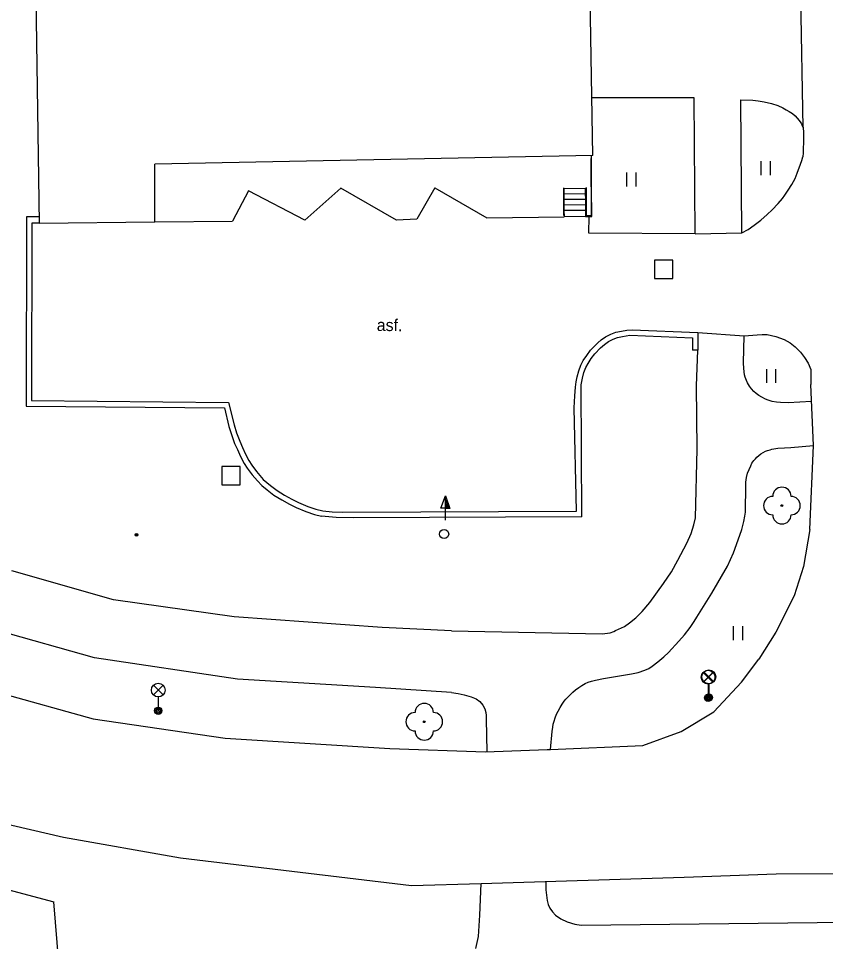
# Model space of a CAD drawing. Extents: x -641829 to -641525, y -1114855 to -1114359.
# Drawn here: x -641625.7 to -641581.7, y -1114535.8 to -1114485.6 of the extents above; entities that cross this region are included whole.
import ezdxf

# ---------------------------------------------------------------- set-up
doc = ezdxf.new("R2010")
doc.units = 0
for name, color, linetype in [('Vrstva 10', 7, 'Continuous'), ('Vrstva 11', 7, 'Continuous'), ('Vrstva 20', 7, 'Continuous'), ('Vrstva 22', 7, 'Continuous'), ('Vrstva 25', 7, 'Continuous'), ('Vrstva 26', 7, 'Continuous'), ('Vrstva 28', 7, 'Continuous'), ('Vrstva 33', 7, 'Continuous'), ('Vrstva 36', 7, 'Continuous'), ('Vrstva 40', 7, 'Continuous'), ('Vrstva 5', 7, 'Continuous'), ('Vrstva 9', 7, 'Continuous')]:
    doc.layers.add(name, color=color, linetype=linetype)

msp = doc.modelspace()

# ---------------------------------------------------------------- linework, layer by layer
at = {"layer": 'Vrstva 10'}
for p, q in [((-641582.96, -1114491.51), (-641583.23, -1114475.12)), ((-641582.96, -1114491.51), (-641582.94, -1114491.78)), ((-641582.94, -1114491.78), (-641582.93, -1114492.28)), ((-641582.93, -1114492.28), (-641582.95, -1114492.71)), ((-641582.95, -1114492.71), (-641582.95, -1114492.89)), ((-641583.09, -1114493.51), (-641583.02, -1114493.3)), ((-641583.02, -1114493.3), (-641582.97, -1114493.1)), ((-641582.95, -1114492.89), (-641582.97, -1114493.1)), ((-641583.27, -1114493.99), (-641583.09, -1114493.51)), ((-641583.57, -1114494.61), (-641583.39, -1114494.29)), ((-641583.39, -1114494.29), (-641583.27, -1114493.99)), ((-641583.76, -1114494.92), (-641583.57, -1114494.61)), ((-641584.08, -1114495.37), (-641583.95, -1114495.19)), ((-641583.95, -1114495.19), (-641583.76, -1114494.92)), ((-641584.64, -1114496), (-641584.31, -1114495.64)), ((-641584.31, -1114495.64), (-641584.08, -1114495.37)), ((-641585.25, -1114496.56), (-641584.91, -1114496.25)), ((-641584.91, -1114496.25), (-641584.64, -1114496)), ((-641594.62, -1114497.26), (-641594.61, -1114496.36)), ((-641585.62, -1114496.83), (-641585.25, -1114496.56)), ((-641588.83, -1114497.3), (-641594.62, -1114497.26)), ((-641588.83, -1114497.3), (-641586.3, -1114497.24)), ((-641586.3, -1114497.24), (-641585.95, -1114497.06)), ((-641585.95, -1114497.06), (-641585.62, -1114496.83)), ((-641588.68, -1114502.68), (-641586.16, -1114502.85)), ((-641586.16, -1114502.85), (-641585.46, -1114502.8)), ((-641585.46, -1114502.8), (-641585.19, -1114502.78)), ((-641585.19, -1114502.78), (-641584.92, -1114502.79)), ((-641582.39, -1114508.83), (-641582.54, -1114505.5)), ((-641582.58, -1114513.41), (-641582.39, -1114508.83)), ((-641582.58, -1114513.41), (-641582.94, -1114515.41)), ((-641582.94, -1114515.41), (-641583.45, -1114517.02)), ((-641583.45, -1114517.02), (-641584.44, -1114519)), ((-641584.44, -1114519), (-641585.36, -1114520.47)), ((-641586.31, -1114521.71), (-641585.36, -1114520.47)), ((-641627.95, -1114521.94), (-641621.63, -1114523.72)), ((-641587.81, -1114523.33), (-641586.31, -1114521.71)), ((-641589.6, -1114524.4), (-641587.81, -1114523.33)), ((-641621.63, -1114523.72), (-641614.43, -1114524.77)), ((-641591.69, -1114525.17), (-641589.6, -1114524.4)), ((-641614.43, -1114524.77), (-641605.47, -1114525.32)), ((-641605.47, -1114525.32), (-641600.26, -1114525.51)), ((-641600.26, -1114525.51), (-641596.9, -1114525.39)), ((-641633.98, -1114527.66), (-641623.24, -1114530.15)), ((-641623.24, -1114530.15), (-641616.87, -1114531.28)), ((-641616.87, -1114531.28), (-641604.29, -1114532.79)), ((-641628.25, -1114532.49), (-641623.76, -1114533.67)), ((-641589.44, -1114532.34), (-641584.42, -1114532.15)), ((-641584.42, -1114532.15), (-641572.24, -1114532.1)), ((-641622.14, -1114553.93), (-641623.76, -1114533.67))]:
    msp.add_line(p, q, dxfattribs=at)
for points in [[(-641596.9, -1114525.39), (-641596.71, -1114525.38), (-641591.69, -1114525.17)], [(-641604.29, -1114532.79), (-641600.49, -1114532.67), (-641589.44, -1114532.34)]]:
    msp.add_lwpolyline(points, dxfattribs=at)
at = {"layer": 'Vrstva 11'}
for p, q in [((-641588.88, -1114489.9), (-641594.45, -1114489.9)), ((-641588.83, -1114497.3), (-641588.88, -1114489.9)), ((-641586.3, -1114497.24), (-641586.35, -1114490)), ((-641586.35, -1114490), (-641585.7, -1114490.02)), ((-641585.7, -1114490.02), (-641585.4, -1114490.05)), ((-641585.4, -1114490.05), (-641585.08, -1114490.11)), ((-641585.08, -1114490.11), (-641584.67, -1114490.21)), ((-641584.67, -1114490.21), (-641584.33, -1114490.32)), ((-641584.33, -1114490.32), (-641584.06, -1114490.44)), ((-641584.06, -1114490.44), (-641583.87, -1114490.54)), ((-641583.87, -1114490.54), (-641583.71, -1114490.63)), ((-641583.71, -1114490.63), (-641583.54, -1114490.75)), ((-641583.54, -1114490.75), (-641583.39, -1114490.88)), ((-641583.39, -1114490.88), (-641583.28, -1114491)), ((-641583.28, -1114491), (-641583.17, -1114491.13)), ((-641583.17, -1114491.13), (-641583.08, -1114491.25)), ((-641583.08, -1114491.25), (-641583.04, -1114491.31)), ((-641583.04, -1114491.31), (-641583, -1114491.42)), ((-641583, -1114491.42), (-641582.96, -1114491.51)), ((-641594.48, -1114494.82), (-641594.49, -1114493.03)), ((-641603.01, -1114494.79), (-641604, -1114496.51)), ((-641603.01, -1114494.79), (-641600.18, -1114496.43)), ((-641595.99, -1114494.83), (-641594.82, -1114494.81)), ((-641594.82, -1114494.81), (-641594.82, -1114495.11)), ((-641613.16, -1114494.95), (-641614.04, -1114496.61)), ((-641610.1, -1114496.56), (-641613.16, -1114494.95)), ((-641608.14, -1114494.82), (-641610.1, -1114496.56)), ((-641605.1, -1114496.56), (-641608.14, -1114494.82)), ((-641595.99, -1114494.83), (-641595.99, -1114495.12)), ((-641595.99, -1114495.12), (-641594.82, -1114495.11)), ((-641595.99, -1114495.12), (-641595.98, -1114495.42)), ((-641594.82, -1114495.11), (-641594.81, -1114495.41)), ((-641594.46, -1114496.36), (-641594.48, -1114494.82)), ((-641595.98, -1114495.42), (-641594.81, -1114495.41)), ((-641595.98, -1114495.42), (-641595.98, -1114495.72)), ((-641595.98, -1114495.72), (-641594.81, -1114495.71)), ((-641595.98, -1114495.72), (-641595.98, -1114496.02)), ((-641594.81, -1114495.41), (-641594.81, -1114495.71)), ((-641594.81, -1114495.71), (-641594.8, -1114496.01)), ((-641595.98, -1114496.02), (-641594.8, -1114496.01)), ((-641595.98, -1114496.02), (-641595.97, -1114496.38)), ((-641594.8, -1114496.01), (-641594.8, -1114496.35)), ((-641625.26, -1114496.37), (-641625.28, -1114506.68)), ((-641624.57, -1114496.37), (-641625.26, -1114496.37)), ((-641624.96, -1114496.72), (-641624.98, -1114506.38)), ((-641624.57, -1114496.72), (-641624.96, -1114496.72)), ((-641618.26, -1114496.64), (-641614.04, -1114496.61)), ((-641604, -1114496.51), (-641605.1, -1114496.56)), ((-641600.18, -1114496.43), (-641595.97, -1114496.38)), ((-641594.8, -1114496.35), (-641595.97, -1114496.38)), ((-641594.8, -1114496.35), (-641594.46, -1114496.36)), ((-641592.39, -1114502.81), (-641588.98, -1114502.97)), ((-641592.27, -1114502.52), (-641588.68, -1114502.68)), ((-641588.68, -1114502.68), (-641588.68, -1114503.64)), ((-641586.2, -1114504.33), (-641586.16, -1114502.85)), ((-641588.98, -1114502.97), (-641588.98, -1114503.64)), ((-641588.68, -1114503.64), (-641588.98, -1114503.64)), ((-641588.77, -1114505.58), (-641588.68, -1114503.64)), ((-641586.18, -1114504.64), (-641586.2, -1114504.33)), ((-641586.14, -1114504.97), (-641586.18, -1114504.64)), ((-641582.54, -1114504.69), (-641582.54, -1114505.5)), ((-641586.11, -1114505.1), (-641586.14, -1114504.97)), ((-641586.04, -1114505.29), (-641586.11, -1114505.1)), ((-641585.98, -1114505.42), (-641586.04, -1114505.29)), ((-641595, -1114512.71), (-641595.05, -1114505.53)), ((-641588.73, -1114509.02), (-641588.77, -1114505.58)), ((-641585.87, -1114505.6), (-641585.98, -1114505.42)), ((-641585.76, -1114505.75), (-641585.87, -1114505.6)), ((-641585.63, -1114505.88), (-641585.76, -1114505.75)), ((-641585.51, -1114505.99), (-641585.63, -1114505.88)), ((-641585.36, -1114506.11), (-641585.51, -1114505.99)), ((-641585.21, -1114506.2), (-641585.36, -1114506.11)), ((-641585, -1114506.3), (-641585.21, -1114506.2)), ((-641584.85, -1114506.36), (-641585, -1114506.3)), ((-641584.64, -1114506.43), (-641584.85, -1114506.36)), ((-641625.28, -1114506.68), (-641614.48, -1114506.78)), ((-641624.98, -1114506.38), (-641614.25, -1114506.48)), ((-641584.4, -1114506.47), (-641584.64, -1114506.43)), ((-641584.18, -1114506.49), (-641584.4, -1114506.47)), ((-641583.76, -1114506.5), (-641584.18, -1114506.49)), ((-641582.5, -1114506.44), (-641583.76, -1114506.5)), ((-641583.63, -1114508.94), (-641582.39, -1114508.83)), ((-641588.82, -1114512.77), (-641588.73, -1114509.02)), ((-641585.47, -1114509.46), (-641585.37, -1114509.38)), ((-641585.37, -1114509.38), (-641585.25, -1114509.28)), ((-641585.25, -1114509.28), (-641585.13, -1114509.21)), ((-641585.13, -1114509.21), (-641585, -1114509.14)), ((-641585, -1114509.14), (-641584.89, -1114509.1)), ((-641584.89, -1114509.1), (-641584.75, -1114509.06)), ((-641584.75, -1114509.06), (-641584.65, -1114509.03)), ((-641584.65, -1114509.03), (-641584.34, -1114508.98)), ((-641584.34, -1114508.98), (-641583.97, -1114508.95)), ((-641583.97, -1114508.95), (-641583.63, -1114508.94)), ((-641585.81, -1114509.94), (-641585.74, -1114509.79)), ((-641585.74, -1114509.79), (-641585.64, -1114509.65)), ((-641585.64, -1114509.65), (-641585.55, -1114509.55)), ((-641585.55, -1114509.55), (-641585.47, -1114509.46)), ((-641586.03, -1114510.57), (-641585.98, -1114510.34)), ((-641585.98, -1114510.34), (-641585.9, -1114510.13)), ((-641585.9, -1114510.13), (-641585.81, -1114509.94)), ((-641586.08, -1114510.99), (-641586.07, -1114510.82)), ((-641586.07, -1114510.82), (-641586.03, -1114510.57)), ((-641586.09, -1114512.46), (-641586.08, -1114510.99)), ((-641588.9, -1114513.14), (-641588.82, -1114512.77)), ((-641586.19, -1114512.96), (-641586.12, -1114512.68)), ((-641586.12, -1114512.68), (-641586.09, -1114512.46)), ((-641589.06, -1114513.62), (-641588.9, -1114513.14)), ((-641586.49, -1114513.97), (-641586.29, -1114513.41)), ((-641586.29, -1114513.41), (-641586.19, -1114512.96)), ((-641589.29, -1114514.15), (-641589.06, -1114513.62)), ((-641589.77, -1114515.08), (-641589.29, -1114514.15)), ((-641586.74, -1114514.67), (-641586.49, -1114513.97)), ((-641587.08, -1114515.39), (-641586.74, -1114514.67)), ((-641590.13, -1114515.71), (-641589.77, -1114515.08)), ((-641587.93, -1114516.87), (-641587.08, -1114515.39)), ((-641620.51, -1114517.23), (-641626.06, -1114515.66)), ((-641590.56, -1114516.35), (-641590.13, -1114515.71)), ((-641591.31, -1114517.38), (-641590.56, -1114516.35)), ((-641588.74, -1114518.17), (-641587.93, -1114516.87)), ((-641613.94, -1114518.16), (-641620.51, -1114517.23)), ((-641591.72, -1114517.87), (-641591.31, -1114517.38)), ((-641592.07, -1114518.22), (-641591.72, -1114517.87)), ((-641605.89, -1114518.74), (-641613.94, -1114518.16)), ((-641592.41, -1114518.49), (-641592.07, -1114518.22)), ((-641589.11, -1114518.73), (-641588.88, -1114518.41)), ((-641588.88, -1114518.41), (-641588.74, -1114518.17)), ((-641621.55, -1114520.39), (-641627.08, -1114518.84)), ((-641602.11, -1114518.92), (-641605.89, -1114518.74)), ((-641602.11, -1114518.92), (-641593.9, -1114519.08)), ((-641593.27, -1114518.95), (-641593.17, -1114518.9)), ((-641593.17, -1114518.9), (-641592.69, -1114518.68)), ((-641592.69, -1114518.68), (-641592.41, -1114518.49)), ((-641589.42, -1114519.13), (-641589.11, -1114518.73)), ((-641593.9, -1114519.08), (-641593.46, -1114519.02)), ((-641593.46, -1114519.02), (-641593.27, -1114518.95)), ((-641589.72, -1114519.48), (-641589.42, -1114519.13)), ((-641590.29, -1114520.1), (-641589.72, -1114519.48)), ((-641613.77, -1114521.55), (-641621.55, -1114520.39)), ((-641590.86, -1114520.61), (-641590.54, -1114520.34)), ((-641590.54, -1114520.34), (-641590.29, -1114520.1)), ((-641591.36, -1114520.97), (-641591.17, -1114520.85)), ((-641591.17, -1114520.85), (-641590.86, -1114520.61)), ((-641593.83, -1114521.52), (-641592.3, -1114521.26)), ((-641592.3, -1114521.26), (-641591.93, -1114521.18)), ((-641591.93, -1114521.18), (-641591.57, -1114521.06)), ((-641591.57, -1114521.06), (-641591.36, -1114520.97)), ((-641606.24, -1114522.01), (-641613.77, -1114521.55)), ((-641595.17, -1114522), (-641595.01, -1114521.89)), ((-641595.01, -1114521.89), (-641594.82, -1114521.79)), ((-641594.82, -1114521.79), (-641594.66, -1114521.72)), ((-641594.66, -1114521.72), (-641594.49, -1114521.66)), ((-641594.49, -1114521.66), (-641594.27, -1114521.61)), ((-641594.27, -1114521.61), (-641593.83, -1114521.52)), ((-641602.11, -1114522.28), (-641606.24, -1114522.01)), ((-641602.11, -1114522.28), (-641601.74, -1114522.33)), ((-641601.74, -1114522.33), (-641601.42, -1114522.4)), ((-641601.42, -1114522.4), (-641601.04, -1114522.52)), ((-641595.77, -1114522.53), (-641595.64, -1114522.4)), ((-641595.64, -1114522.4), (-641595.5, -1114522.26)), ((-641595.5, -1114522.26), (-641595.35, -1114522.14)), ((-641595.35, -1114522.14), (-641595.17, -1114522)), ((-641601.04, -1114522.52), (-641600.76, -1114522.63)), ((-641600.76, -1114522.63), (-641600.57, -1114522.77)), ((-641600.57, -1114522.77), (-641600.4, -1114522.97)), ((-641596.19, -1114523.09), (-641596.08, -1114522.92)), ((-641596.08, -1114522.92), (-641595.97, -1114522.75)), ((-641595.97, -1114522.75), (-641595.87, -1114522.64)), ((-641595.87, -1114522.64), (-641595.77, -1114522.53)), ((-641600.4, -1114522.97), (-641600.29, -1114523.17)), ((-641600.29, -1114523.17), (-641600.24, -1114523.37)), ((-641600.24, -1114523.37), (-641600.22, -1114523.53)), ((-641596.46, -1114523.66), (-641596.38, -1114523.45)), ((-641596.38, -1114523.45), (-641596.3, -1114523.29)), ((-641596.3, -1114523.29), (-641596.19, -1114523.09)), ((-641600.22, -1114523.53), (-641600.22, -1114523.73)), ((-641600.22, -1114523.73), (-641600.18, -1114525.51)), ((-641596.56, -1114524.01), (-641596.52, -1114523.83)), ((-641596.52, -1114523.83), (-641596.46, -1114523.66)), ((-641596.71, -1114525.38), (-641596.62, -1114524.41)), ((-641596.62, -1114524.41), (-641596.59, -1114524.17)), ((-641596.59, -1114524.17), (-641596.56, -1114524.01)), ((-641600.56, -1114534.4), (-641600.49, -1114532.67)), ((-641596.97, -1114532.57), (-641596.96, -1114533.03)), ((-641596.96, -1114533.03), (-641596.9, -1114533.6)), ((-641596.9, -1114533.6), (-641596.84, -1114533.82)), ((-641596.84, -1114533.82), (-641596.75, -1114534.02)), ((-641596.75, -1114534.02), (-641596.61, -1114534.23)), ((-641600.64, -1114535.57), (-641600.56, -1114534.4)), ((-641596.61, -1114534.23), (-641596.44, -1114534.41)), ((-641596.44, -1114534.41), (-641596.15, -1114534.61)), ((-641596.15, -1114534.61), (-641595.8, -1114534.77)), ((-641595.8, -1114534.77), (-641595.38, -1114534.9)), ((-641595.38, -1114534.9), (-641595.05, -1114534.95)), ((-641595.05, -1114534.95), (-641569.23, -1114534.66)), ((-641600.78, -1114536.22), (-641600.64, -1114535.57))]:
    msp.add_line(p, q, dxfattribs=at)
for points in [[(-641594.29, -1114503.38), (-641594.14, -1114503.23), (-641593.95, -1114503.08), (-641593.71, -1114502.91), (-641593.42, -1114502.77), (-641593.16, -1114502.66), (-641592.85, -1114502.6), (-641592.56, -1114502.54), (-641592.27, -1114502.52)], [(-641593.99, -1114503.5), (-641593.77, -1114503.32), (-641593.55, -1114503.17), (-641593.3, -1114503.04), (-641593.07, -1114502.95), (-641592.79, -1114502.89), (-641592.39, -1114502.81)], [(-641584.92, -1114502.79), (-641584.44, -1114502.89), (-641583.98, -1114503.05), (-641583.66, -1114503.24), (-641583.38, -1114503.45), (-641583.09, -1114503.74), (-641582.88, -1114504.03), (-641582.68, -1114504.34), (-641582.54, -1114504.69)], [(-641595.35, -1114505.65), (-641595.32, -1114505.36), (-641595.27, -1114505.09), (-641595.18, -1114504.76), (-641595.06, -1114504.45), (-641594.93, -1114504.2), (-641594.74, -1114503.92), (-641594.53, -1114503.63), (-641594.29, -1114503.38)], [(-641595.05, -1114505.53), (-641594.97, -1114505.16), (-641594.9, -1114504.85), (-641594.79, -1114504.58), (-641594.67, -1114504.36), (-641594.5, -1114504.09), (-641594.3, -1114503.83), (-641593.99, -1114503.5)], [(-641595.3, -1114512.41), (-641595.42, -1114506.78), (-641595.39, -1114506.12), (-641595.35, -1114505.65)], [(-641614.48, -1114506.78), (-641614.23, -1114507.79), (-641614.13, -1114508.12), (-641614.02, -1114508.44)], [(-641614.25, -1114506.48), (-641613.94, -1114507.71), (-641613.81, -1114508.13)], [(-641613.81, -1114508.13), (-641613.64, -1114508.6), (-641613.5, -1114508.93), (-641613.33, -1114509.29), (-641613.14, -1114509.65), (-641612.99, -1114509.89), (-641612.73, -1114510.25), (-641612.36, -1114510.67)], [(-641614.02, -1114508.44), (-641613.92, -1114508.72), (-641613.77, -1114509.05), (-641613.6, -1114509.42), (-641613.4, -1114509.8), (-641613.23, -1114510.06), (-641612.96, -1114510.43), (-641612.68, -1114510.75), (-641612.43, -1114511)], [(-641612.36, -1114510.67), (-641611.96, -1114511.01), (-641611.61, -1114511.28), (-641611.2, -1114511.53), (-641610.8, -1114511.75), (-641610.44, -1114511.94), (-641609.93, -1114512.15), (-641609.49, -1114512.29), (-641609.12, -1114512.38)], [(-641612.43, -1114511), (-641612.15, -1114511.25), (-641611.78, -1114511.53), (-641611.35, -1114511.79), (-641610.94, -1114512.02), (-641610.56, -1114512.21), (-641610.04, -1114512.43), (-641609.57, -1114512.58), (-641609.19, -1114512.67)], [(-641609.12, -1114512.38), (-641608.6, -1114512.44), (-641608.03, -1114512.45), (-641595.3, -1114512.41)], [(-641595, -1114512.71), (-641607.47, -1114512.76), (-641608.39, -1114512.75), (-641608.79, -1114512.72), (-641609.19, -1114512.67)]]:
    msp.add_lwpolyline(points, dxfattribs=at)
at = {"layer": 'Vrstva 20'}
for radius in [0.075, 0.0204]:
    msp.add_circle((-641619.26, -1114513.69), radius, dxfattribs=at)
at = {"layer": 'Vrstva 22'}
for centre in [(-641584.11, -1114512.1), (-641603.59, -1114523.87)]:
    msp.add_circle(centre, 0.05, dxfattribs=at)
for centre, start, end in [((-641584.11, -1114511.6), 0, 180), ((-641584.61, -1114512.1), 90, 270), ((-641583.61, -1114512.1), 270, 90), ((-641584.11, -1114512.6), 180, 0), ((-641603.59, -1114523.37), 0, 180), ((-641604.09, -1114523.87), 90, 270), ((-641603.09, -1114523.87), 270, 90), ((-641603.59, -1114524.37), 180, 0)]:
    msp.add_arc(centre, 0.5, start, end, dxfattribs=at)
at = {"layer": 'Vrstva 25'}
for p, q in [((-641602.692, -1114512.248), (-641602.44, -1114511.574)), ((-641602.44, -1114512.248), (-641602.692, -1114512.248)), ((-641602.44, -1114512.9), (-641602.44, -1114512.25))]:
    msp.add_line(p, q, dxfattribs=at)
for points in [[(-641602.19, -1114512.25), (-641602.44, -1114512.25), (-641602.44, -1114511.574), (-641602.44, -1114511.574)], [(-641602.248, -1114512.21), (-641602.4, -1114512.21), (-641602.4, -1114511.796)], [(-641602.304, -1114512.17), (-641602.36, -1114512.17), (-641602.36, -1114512.02)]]:
    msp.add_lwpolyline(points, close=True, dxfattribs=at)
at = {"layer": 'Vrstva 26'}
for points in [[(-641591.05, -1114499.74), (-641590.05, -1114499.74), (-641590.05, -1114498.74), (-641591.05, -1114498.74)], [(-641613.61, -1114509.97), (-641614.61, -1114509.97), (-641614.61, -1114510.97), (-641613.61, -1114510.97)]]:
    msp.add_lwpolyline(points, close=True, dxfattribs=at)
at = {"layer": 'Vrstva 28'}
msp.add_circle((-641602.51, -1114513.65), 0.25, dxfattribs=at)
at = {"layer": 'Vrstva 33'}
for p, q in [((-641588.394, -1114521.71), (-641587.866, -1114521.18)), ((-641588.394, -1114521.18), (-641587.866, -1114521.71)), ((-641588.354, -1114521.69), (-641587.826, -1114521.16)), ((-641588.354, -1114521.16), (-641587.826, -1114521.69)), ((-641618.344, -1114522.41), (-641617.816, -1114521.88)), ((-641618.344, -1114521.88), (-641617.816, -1114522.41)), ((-641588.13, -1114521.82), (-641588.13, -1114522.57)), ((-641588.09, -1114521.8), (-641588.09, -1114522.55)), ((-641618.08, -1114522.52), (-641618.08, -1114523.27))]:
    msp.add_line(p, q, dxfattribs=at)
for centre, radius in [((-641588.13, -1114521.445), 0.375), ((-641588.09, -1114521.425), 0.375), ((-641618.08, -1114522.145), 0.375), ((-641588.13, -1114522.57), 0.2), ((-641588.09, -1114522.55), 0.2), ((-641588.13, -1114522.57), 0.145), ((-641588.09, -1114522.55), 0.145), ((-641588.13, -1114522.57), 0.0876), ((-641588.09, -1114522.55), 0.0876), ((-641618.08, -1114523.27), 0.2), ((-641618.08, -1114523.27), 0.145), ((-641618.08, -1114523.27), 0.0876)]:
    msp.add_circle(centre, radius, dxfattribs=at)
at = {"layer": 'Vrstva 36'}
for p, q in [((-641585.234, -1114494.104), (-641585.234, -1114493.352)), ((-641584.734, -1114494.104), (-641584.734, -1114493.352)), ((-641592.554, -1114494.714), (-641592.554, -1114493.962)), ((-641592.054, -1114494.714), (-641592.054, -1114493.962)), ((-641584.934, -1114505.412), (-641584.934, -1114504.664)), ((-641584.434, -1114505.412), (-641584.434, -1114504.664)), ((-641586.744, -1114519.422), (-641586.744, -1114518.674)), ((-641586.244, -1114519.422), (-641586.244, -1114518.674))]:
    msp.add_line(p, q, dxfattribs=at)
at = {"layer": 'Vrstva 5'}
for p, q in [((-641594.4, -1114493.03), (-641595.25, -1114444.98)), ((-641625.33, -1114445.45), (-641624.57, -1114496.72)), ((-641594.4, -1114493.03), (-641618.27, -1114493.51)), ((-641618.26, -1114496.64), (-641618.27, -1114493.51)), ((-641624.57, -1114496.72), (-641618.26, -1114496.64))]:
    msp.add_line(p, q, dxfattribs=at)
at = {"layer": 'Vrstva 9'}
for p, q in [((-641594.51, -1114493.2), (-641594.5, -1114496.31)), ((-641596.01, -1114494.79), (-641596, -1114496.3)), ((-641594.75, -1114496.32), (-641594.75, -1114494.78)), ((-641594.5, -1114496.31), (-641594.75, -1114496.32))]:
    msp.add_line(p, q, dxfattribs=at)

# ---------------------------------------------------------------- texts
at = {"layer": 'Vrstva 40'}
msp.add_text('asf.', height=0.6499, rotation=359.4695, dxfattribs=at).set_placement((-641606.18, -1114502.59))

doc.saveas('drawing.dxf')
